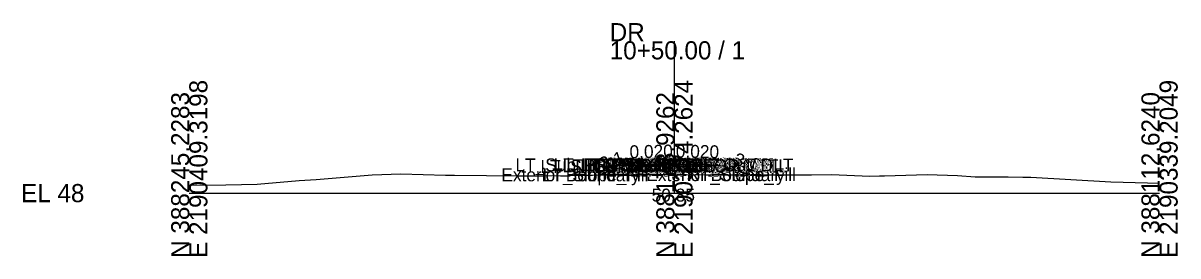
# Model space of a CAD drawing. Extents: x -26 to 153, y -10 to 1035.
# Drawn here: x -25.7 to 152.8, y 490.3 to 526.2 of the extents above; entities that cross this region are included whole.
import ezdxf

# ---------------------------------------------------------------- set-up
doc = ezdxf.new("R2010")
doc.units = 0
for name, color, linetype in [('Default', 7, 'Continuous'), ('Exist CMT Ground Line', 7, 'Continuous'), ('Exist Cross Section Cell', 7, 'Continuous'), ('Exist XS Center Line Elevation Label', 7, 'Continuous'), ('Prop CMT Pvmt Course 1', 7, 'Continuous'), ('Prop CMT Pvmt Course 2', 7, 'Continuous'), ('Prop CMT Pvmt Surface', 7, 'Continuous'), ('Prop CMT Shld Paved Course 1', 7, 'Continuous'), ('Prop CMT Shld Paved Course 2', 7, 'Continuous'), ('Prop CMT Slope Grass', 7, 'Continuous'), ('Prop CMT Subgrade Earthwork', 7, 'Continuous'), ('Prop XS SE Text', 7, 'Continuous'), ('Prop XS Side Slope Text', 7, 'Continuous'), ('Scratch_Level_1', 7, 'Continuous')]:
    doc.layers.add(name, color=color, linetype=linetype)

msp = doc.modelspace()

# ---------------------------------------------------------------- linework, layer by layer
at = {"layer": 'Exist CMT Ground Line'}
for p, q in [((10.49, 501.4), (16.98, 501.93)), ((16.98, 501.93), (19.63, 502.12)), ((19.63, 502.12), (28.29, 502.81)), ((28.29, 502.81), (32.69, 502.99)), ((32.69, 502.99), (39.6, 502.78)), ((39.6, 502.78), (41.02, 502.78)), ((41.02, 502.78), (50.91, 502.69)), ((50.91, 502.69), (54.89, 502.67)), ((54.89, 502.67), (66.03, 502.83)), ((66.03, 502.83), (69.35, 502.88)), ((69.35, 502.88), (71.06, 502.85)), ((71.06, 502.85), (75, 502.85)), ((75, 502.85), (79.67, 502.84)), ((79.67, 502.84), (86.77, 502.82)), ((86.77, 502.82), (96.17, 502.81)), ((96.17, 502.81), (99.29, 502.88)), ((99.29, 502.88), (105.21, 502.64)), ((105.21, 502.64), (106.69, 502.66)), ((106.69, 502.66), (107.48, 502.66)), ((107.48, 502.66), (114.09, 502.87)), ((114.09, 502.87), (118.79, 502.71)), ((118.79, 502.71), (121.49, 502.51)), ((121.49, 502.51), (126.6, 502.52)), ((126.6, 502.52), (128.89, 502.45)), ((128.89, 502.45), (130.1, 502.44)), ((130.1, 502.44), (142.45, 501.76)), ((142.45, 501.76), (148.13, 501.58)), ((0, 501.22), (5.66, 501.28)), ((5.66, 501.28), (10.49, 501.4)), ((148.13, 501.58), (150, 501.56))]:
    msp.add_line(p, q, dxfattribs=at)
at = {"layer": 'Exist Cross Section Cell'}
for p, q in [((75, 500), (75, 523.45)), ((0, 500), (75, 500)), ((75, 500), (150, 500))]:
    msp.add_line(p, q, dxfattribs=at)
at = {"layer": 'Prop CMT Pvmt Course 1'}
for points in [[(75, 504.48), (69.5, 504.37)], [(69.5, 504.36), (75, 504.47)], [(69.5, 504.37), (69.5, 504.36)], [(75, 504.47), (75, 504.48)], [(75, 504.48), (80.5, 504.37)], [(75, 504.47), (75, 504.48)], [(80.5, 504.36), (75, 504.47)], [(80.5, 504.37), (80.5, 504.36)]]:
    msp.add_lwpolyline(points, dxfattribs=at)
msp.add_lwpolyline([(75, 504.47), (75, 504.36), (75, 504.36), (75, 504.47)], close=True, dxfattribs=at)
msp.add_lwpolyline([(75, 504.47), (75, 504.36), (75, 504.36), (75, 504.47)], close=True, dxfattribs=at)
at = {"layer": 'Prop CMT Pvmt Course 2'}
for points in [[(75, 504.47), (69.5, 504.36)], [(69.5, 504.36), (69.5, 504.11)], [(69.5, 504.11), (75, 504.22)], [(75, 504.22), (75, 504.47)], [(75, 504.22), (75, 504.47)], [(75, 504.47), (80.5, 504.36)], [(80.5, 504.11), (75, 504.22)], [(80.5, 504.36), (80.5, 504.11)]]:
    msp.add_lwpolyline(points, dxfattribs=at)
at = {"layer": 'Prop CMT Pvmt Surface'}
for points in [[(75, 504.48), (69.5, 504.37)], [(75, 504.48), (80.5, 504.37)]]:
    msp.add_lwpolyline(points, dxfattribs=at)
at = {"layer": 'Prop CMT Shld Paved Course 1'}
for points in [[(69.5, 504.37), (69.49, 504.36)], [(69.49, 504.36), (69.5, 504.36)], [(69.5, 504.36), (69.5, 504.37)], [(80.5, 504.37), (80.51, 504.36)], [(80.5, 504.36), (80.5, 504.37)], [(80.51, 504.36), (80.5, 504.36)]]:
    msp.add_lwpolyline(points, dxfattribs=at)
at = {"layer": 'Prop CMT Shld Paved Course 2'}
for points in [[(69.5, 504.36), (69.49, 504.36), (69.49, 504.36), (69.23, 504.11)], [(69.23, 504.11), (69.5, 504.11)], [(69.5, 504.11), (69.5, 504.36)], [(80.5, 504.36), (80.51, 504.36), (80.51, 504.36), (80.77, 504.11)], [(80.5, 504.11), (80.5, 504.36)], [(80.77, 504.11), (80.5, 504.11)]]:
    msp.add_lwpolyline(points, dxfattribs=at)
at = {"layer": 'Prop CMT Slope Grass'}
for p, q in [((67.5, 504.21), (63.23, 502.79)), ((69.5, 504.37), (67.5, 504.21)), ((80.5, 504.37), (82.5, 504.21)), ((82.5, 504.21), (86.68, 502.82))]:
    msp.add_line(p, q, dxfattribs=at)
at = {"layer": 'Prop CMT Subgrade Earthwork'}
for points in [[(69.5, 504.11), (69.23, 504.11), (69.01, 504.33)], [(75, 504.22), (69.5, 504.11)], [(75, 504.22), (80.5, 504.11)], [(80.5, 504.11), (80.77, 504.11), (80.99, 504.33)]]:
    msp.add_lwpolyline(points, dxfattribs=at)

# ---------------------------------------------------------------- texts
at = {"layer": 'Default'}
msp.add_text('-', height=0.0001, dxfattribs=at).set_placement((0, 500))
at = {"layer": 'Exist Cross Section Cell'}
for s, p in [('DR', (65, 523.45)), ('10+50.00 / 1', (65, 520.65)), ('EL 48', (-26, 498.6))]:
    msp.add_text(s, height=2.8, dxfattribs=at).set_placement(p)
for s, p in [('E 2190409.3198', (2.8, 490)), ('E 2190374.2624', (77.8, 490)), ('E 2190339.2049', (152.8, 490)), ('N 388245.2283', (0, 490)), ('N 388178.9262', (75, 490)), ('N 388112.6240', (150, 490))]:
    msp.add_text(s, height=2.8, rotation=90, dxfattribs=at).set_placement(p)
at = {"layer": 'Exist XS Center Line Elevation Label'}
msp.add_text('50.85', height=2, dxfattribs=at).set_placement((71.48, 498.69))
at = {"layer": 'Prop XS SE Text'}
for rotation, p in [(1.1458, (68.08, 505.37)), (358.8542, (75.2, 505.5))]:
    msp.add_text('0.020', height=2, rotation=rotation, dxfattribs=at).set_placement(p)
at = {"layer": 'Prop XS Side Slope Text'}
for rotation, p in [(18.4332, (63.85, 503.48)), (341.5668, (84.03, 504.41))]:
    msp.add_text('3:1', height=2, rotation=rotation, dxfattribs=at).set_placement(p)
at = {"layer": 'Scratch_Level_1'}
for s, p in [('LT_Sub_Trench_Out_DLT', (50.42, 503.35)), ('LT_PS2_Shelf_Out', (56.32, 503.38)), ('LT_GS_OS_CTL', (57.72, 503.23)), ('LT_PV2_OEOT', (60.52, 503.38)), ('LT_PS2_OEOP', (60.58, 503.38)), ('LT_PV1_OEOT', (61.09, 503.39)), ('RT_Sub_Trench_Out_DLT', (61.43, 503.34)), ('RT_Sub_OEEOP', (64.17, 503.22)), ('LT_Sub_OEEOP', (64.21, 503.22)), ('RT_PV2_OEEOP', (64.26, 503.47)), ('LT_PV2_OEEOP', (64.31, 503.47)), ('RT_PV1_OEEOP', (64.83, 503.36)), ('LT_PV1_OEEOP', (64.87, 503.36)), ('RT_PV2_IEEOP', (64.91, 503.47)), ('LT_PV2_IEEOP', (64.95, 503.47)), ('RT_PV1_IEEOP', (65.47, 503.36)), ('LT_PV1_IEEOP', (65.52, 503.36)), ('RT_PS2_Shelf_Out', (66.37, 503.36)), ('PV2_PGL', (68.91, 503.47)), ('PV1_PGL', (69.47, 503.48)), ('RT_PV2_OEOT', (70.55, 503.37)), ('RT_PS2_OEOP', (70.62, 503.36)), ('RT_PV1_OEOT', (71.11, 503.38)), ('Exterior Boundary', (48.25, 501.82)), ('LT_Sub_Trench_Out', (54.29, 503.13)), ('LT_Slope_Fill', (54.63, 501.82)), ('LT_Sub_OEOT', (60.43, 503.13)), ('RT_Sub_Trench_Out', (64.84, 503.11)), ('RT_Sub_OEOT', (70.45, 503.12)), ('Exterior Boundary', (70.66, 501.85)), ('RT_GS_OS_CTL', (71.74, 503.22)), ('RT_Slope_Fill', (76.99, 501.85))]:
    msp.add_text(s, height=2, dxfattribs=at).set_placement(p)

doc.saveas('drawing.dxf')
